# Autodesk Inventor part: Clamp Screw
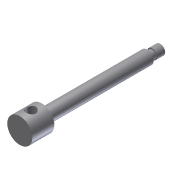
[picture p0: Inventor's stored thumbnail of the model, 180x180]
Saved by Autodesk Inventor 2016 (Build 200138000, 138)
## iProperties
Shininess: 77.0
Length Units: 11269
Angle Units: 11279
Time Units: 11290
Mass Units: 11283
Length Display Precision: 3
Angle Display Precision: 2
Created: 2002-02
Part Number: Clamp Screw
Document SubType Name: Modeling
Designer: ***
Density: 1 g/cm^3
Material: Generic
Appearance: Default
Density: 0.0
Volumn: 0.0
Area: 0.0
PropertySet Name: Model Information
Control State: 0
Master: False
Checked Out: False
Author: ***
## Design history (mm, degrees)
sketch "Sketch1"
  geometry: L1 (0, 140)-(5, 140); L2 (5, 140)-(5, 132); L3 (5, 132)-(4, 132); L4 (4, 132)-(4, 127); L5 (4, 127)-(6.5, 127); L6 (6.5, 127)-(6.5, 25); L7 (6.5, 25)-(4, 25); L8 (4, 25)-(4, 22); L9 (4, 22)-(12.5, 22); L10 (12.5, 22)-(12.5, 0); L11 (12.5, 0)-(0, 0); L12 (0, 0)-(0, 140)
  constraints: 24 end point, 10 parallel, 1 horizontal, 1 perpendicular
  dimensions: "d0" = 10 diameter of L2 L12; "d1" = 8 diameter of L4 L12; "d2" = 13 diameter of L6 L12; "d3" = 8 diameter of L7.end L12; "d4" = 25 diameter of L10 L12; "d5" = 3 distance from line of L7.end L9; "d6" = 8 distance of L1.end L2.end; "d7" = 13 vertical distance of L1.end L5.end; "d8" = 22 distance of L9.end L10.end; "d10" = 102 distance of L5.end L6.end
revolve "Revolution1" sketch "Sketch1" stored, may be unused: angle "d11" = 90 deg
sketch "Sketch3"
  geometry: L1 (-12.5, 0)-(12.5, 0) reference; C1 r 5 at (-0.113, 11)
  constraints: 1 centre point
  dimensions: "d13" = 10 diameter of C1; "d14" = 11 distance from line of L1 C1.centre
extrude "Extrusion1" cut sketch "Sketch3" stored distance "d15" = 10; taper "d16" = 0 deg
body "Solid1"
